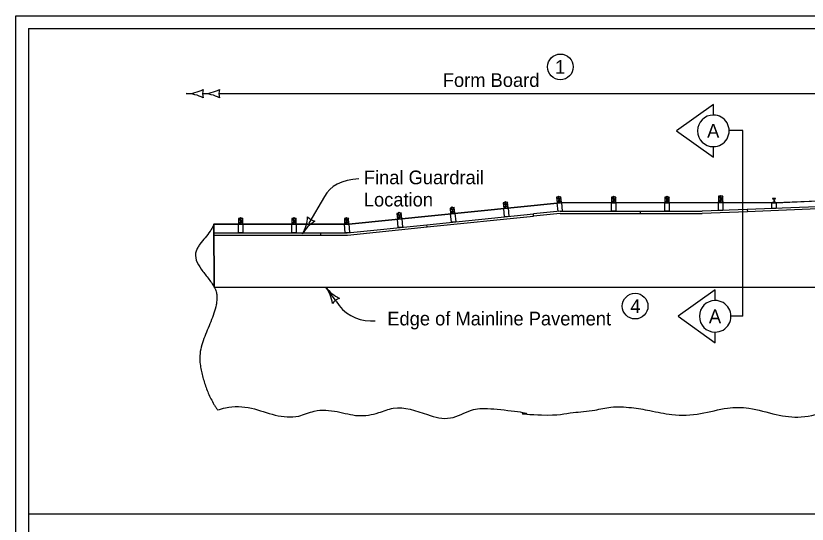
# Model space of a CAD drawing. Extents: x 9538 to 81668, y 7600 to 11751.
# Drawn here: x 10133 to 11058, y 9349 to 9944 of the extents above; entities that cross this region are included whole.
import ezdxf

# ---------------------------------------------------------------- set-up
doc = ezdxf.new("R2010")
doc.units = 0
for name, color, linetype in [('Default', 7, 'Continuous'), ('DsnShtMinorGrid13', 7, 'Continuous'), ('DsnShtMinorGrid14', 7, 'Continuous'), ('dsnStdCells', 7, 'Continuous'), ('dsnStdDimension', 7, 'Continuous'), ('dsnStdNameDate', 7, 'Continuous'), ('dsnStdNote', 7, 'Continuous'), ('dsnStdPattern', 7, 'Continuous'), ('dsnStdShading', 7, 'Continuous'), ('dsnStdTable', 7, 'Continuous')]:
    doc.layers.add(name, color=color, linetype=linetype)

msp = doc.modelspace()

# ---------------------------------------------------------------- linework, layer by layer
at = {"layer": 'Default'}
msp.add_lwpolyline([(10132.52, 9944.02), (13267.53, 9944.02), (13267.53, 7924.02), (10132.52, 7924.02)], close=True, dxfattribs=at)
at = {"layer": 'DsnShtMinorGrid13'}
for centre in [(10769.19, 9884.28), (10856.61, 9604.4)]:
    msp.add_circle(centre, 15, dxfattribs=at)
at = {"layer": 'DsnShtMinorGrid14'}
for p, q in [((10956.48, 9733.86), (10956.48, 9733.93)), ((10702.37, 9725.42), (10708.01, 9719.29)), ((10707.34, 9725.92), (10703.04, 9718.79)), ((10704.76, 9726.64), (10704.75, 9726.71)), ((10705.52, 9719.04), (10704.86, 9725.67)), ((10764.83, 9731.7), (10770.47, 9725.56)), ((10769.81, 9732.2), (10765.5, 9725.07)), ((10765.5, 9725.07), (10770.48, 9725.56)), ((10767.99, 9725.32), (10765.5, 9725.07)), ((10767.99, 9725.32), (10765.5, 9725.07)), ((10766.49, 9715.11), (10765.5, 9725.07)), ((10767.22, 9732.92), (10767.22, 9732.99)), ((10767.98, 9725.32), (10767.32, 9731.95)), ((10770.48, 9725.56), (10771.47, 9715.61)), ((10828.98, 9732.03), (10833.98, 9725.37)), ((10833.98, 9732.03), (10828.98, 9725.37)), ((10828.98, 9725.37), (10833.98, 9725.37)), ((10828.98, 9715.36), (10828.98, 9725.37)), ((10831.48, 9733), (10831.48, 9733.07)), ((10831.48, 9725.37), (10831.48, 9732.03)), ((10833.98, 9725.37), (10833.98, 9715.36)), ((10891.48, 9732.03), (10896.48, 9725.37)), ((10896.48, 9732.03), (10891.48, 9725.37)), ((10891.48, 9725.37), (10896.49, 9725.37)), ((10891.48, 9715.36), (10891.48, 9725.37)), ((10893.98, 9733), (10893.98, 9733.07)), ((10893.98, 9725.37), (10893.98, 9732.03)), ((10896.49, 9725.37), (10896.49, 9715.36)), ((10953.98, 9732.89), (10958.98, 9726.23)), ((10958.98, 9732.89), (10953.98, 9726.23)), ((10953.98, 9726.23), (10958.99, 9726.23)), ((10953.98, 9716.22), (10953.98, 9726.23)), ((10956.48, 9726.23), (10956.48, 9732.89)), ((10958.99, 9726.23), (10958.99, 9716.22)), ((10640.18, 9719.17), (10645.82, 9713.04)), ((10645.16, 9719.67), (10640.85, 9712.54)), ((10642.57, 9720.39), (10642.57, 9720.46)), ((10643.34, 9712.79), (10642.67, 9719.42)), ((10703.04, 9718.79), (10708.02, 9719.29)), ((10704.04, 9708.83), (10703.04, 9718.79)), ((10708.02, 9719.29), (10709.02, 9709.33)), ((10768.98, 9715.36), (10737.62, 9712.2)), ((10771.47, 9715.61), (10766.49, 9715.11)), ((10768.98, 9715.36), (10862.73, 9715.36)), ((10833.98, 9715.36), (10828.98, 9715.36)), ((10862.73, 9712.64), (10862.73, 9715.36)), ((10862.73, 9715.36), (10934.97, 9715.36)), ((10862.73, 9712.65), (10862.73, 9715.36)), ((10896.49, 9715.36), (10891.48, 9715.36)), ((10958.99, 9716.22), (10953.98, 9716.22)), ((10392.74, 9706.96), (10397.74, 9700.29)), ((10397.74, 9706.96), (10392.74, 9700.29)), ((10395.24, 9707.93), (10395.24, 9708)), ((10395.24, 9700.29), (10395.24, 9706.96)), ((10455.24, 9706.96), (10460.24, 9700.29)), ((10460.24, 9706.96), (10455.24, 9700.29)), ((10457.74, 9707.93), (10457.74, 9708)), ((10457.74, 9700.29), (10457.74, 9706.96)), ((10516.63, 9707.02), (10521.95, 9700.58)), ((10521.62, 9707.27), (10516.96, 9700.33)), ((10519.08, 9708.12), (10519.07, 9708.19)), ((10519.46, 9700.45), (10519.12, 9707.15)), ((10578, 9712.96), (10583.64, 9706.79)), ((10582.98, 9713.46), (10578.67, 9706.29)), ((10578.67, 9706.29), (10583.65, 9706.79)), ((10579.66, 9696.28), (10578.67, 9706.29)), ((10580.4, 9714.18), (10580.39, 9714.25)), ((10581.16, 9706.54), (10580.49, 9713.21)), ((10583.65, 9706.79), (10584.64, 9696.78)), ((10613.25, 9699.7), (10737.62, 9712.2)), ((10613.52, 9697.01), (10737.89, 9709.51)), ((10640.85, 9712.54), (10645.83, 9713.04)), ((10641.85, 9702.58), (10640.85, 9712.54)), ((10645.83, 9713.04), (10646.83, 9703.08)), ((10709.02, 9709.33), (10704.04, 9708.83)), ((10737.89, 9709.51), (10737.62, 9712.2)), ((10737.89, 9709.52), (10737.62, 9712.2)), ((10768.98, 9712.65), (10737.89, 9709.52)), ((10768.98, 9712.65), (10862.73, 9712.65)), ((10862.73, 9712.65), (10934.99, 9712.65)), ((10392.74, 9700.29), (10397.74, 9700.29)), ((10392.74, 9690.28), (10392.74, 9700.29)), ((10397.74, 9700.29), (10397.74, 9690.28)), ((10455.24, 9700.29), (10460.24, 9700.29)), ((10455.24, 9690.28), (10455.24, 9700.29)), ((10460.24, 9700.29), (10460.24, 9690.28)), ((10516.96, 9700.33), (10521.96, 9700.58)), ((10517.46, 9690.28), (10516.96, 9700.33)), ((10519.97, 9690.28), (10613.25, 9699.7)), ((10520.24, 9687.57), (10613.52, 9697)), ((10521.96, 9700.58), (10522.45, 9690.53)), ((10584.64, 9696.78), (10579.66, 9696.28)), ((10613.52, 9697), (10613.25, 9699.7)), ((10613.52, 9697.01), (10613.25, 9699.7)), ((10646.83, 9703.08), (10641.85, 9702.58)), ((10363.99, 9690.28), (10488.99, 9690.28)), ((10363.99, 9687.57), (10363.99, 9690.28)), ((10363.99, 9687.57), (10488.99, 9687.57)), ((10397.74, 9690.28), (10392.74, 9690.28)), ((10460.24, 9690.28), (10455.24, 9690.28)), ((10488.99, 9690.28), (10519.97, 9690.28)), ((10488.99, 9687.57), (10488.99, 9690.28)), ((10488.99, 9687.57), (10520.24, 9687.57)), ((10522.45, 9690.53), (10517.46, 9690.28))]:
    msp.add_line(p, q, dxfattribs=at)
for points in [[(10956.29, 9733.32), (10956.29, 9733.86), (10956.68, 9733.86), (10956.68, 9733.32)], [(10704.53, 9725.64), (10704.48, 9726.07), (10705.15, 9726.13), (10705.19, 9725.7)], [(10704.62, 9726.08), (10704.57, 9726.62), (10704.95, 9726.66), (10705.01, 9726.12)], [(10766.99, 9731.92), (10766.95, 9732.34), (10767.61, 9732.41), (10767.65, 9731.98)], [(10767.09, 9732.36), (10767.03, 9732.9), (10767.42, 9732.94), (10767.47, 9732.4)], [(10831.15, 9732.03), (10831.15, 9732.46), (10831.81, 9732.46), (10831.81, 9732.03)], [(10831.29, 9732.46), (10831.29, 9733), (10831.68, 9733), (10831.68, 9732.46)], [(10893.65, 9732.03), (10893.65, 9732.46), (10894.32, 9732.46), (10894.32, 9732.03)], [(10893.79, 9732.46), (10893.79, 9733), (10894.18, 9733), (10894.18, 9732.46)], [(10956.15, 9732.89), (10956.15, 9733.32), (10956.82, 9733.32), (10956.82, 9732.89)], [(10642.34, 9719.39), (10642.3, 9719.82), (10642.96, 9719.88), (10643, 9719.45)], [(10642.43, 9719.83), (10642.38, 9720.37), (10642.77, 9720.41), (10642.82, 9719.87)], [(10394.9, 9706.96), (10394.9, 9707.39), (10395.57, 9707.39), (10395.57, 9706.96)], [(10395.04, 9707.39), (10395.04, 9707.93), (10395.43, 9707.93), (10395.43, 9707.39)], [(10457.4, 9706.96), (10457.4, 9707.39), (10458.07, 9707.39), (10458.07, 9706.96)], [(10457.54, 9707.39), (10457.54, 9707.93), (10457.93, 9707.93), (10457.93, 9707.39)], [(10518.79, 9707.13), (10518.77, 9707.56), (10519.44, 9707.59), (10519.46, 9707.16)], [(10518.91, 9707.57), (10518.88, 9708.11), (10519.27, 9708.13), (10519.3, 9707.59)], [(10580.16, 9713.17), (10580.12, 9713.61), (10580.78, 9713.67), (10580.82, 9713.24)], [(10580.26, 9713.62), (10580.2, 9714.16), (10580.59, 9714.2), (10580.64, 9713.66)], [(10519.46, 9700.45), (10516.96, 9700.33), (10516.96, 9700.33)]]:
    msp.add_lwpolyline(points, dxfattribs=at)
for points in [[(10703.04, 9718.79), (10708.01, 9719.29), (10707.34, 9725.92), (10702.37, 9725.42)], [(10765.5, 9725.07), (10770.47, 9725.56), (10769.81, 9732.2), (10764.83, 9731.7)], [(10828.98, 9725.37), (10833.98, 9725.37), (10833.98, 9732.03), (10828.98, 9732.03)], [(10891.48, 9725.37), (10896.48, 9725.37), (10896.48, 9732.03), (10891.48, 9732.03)], [(10953.98, 9726.23), (10958.98, 9726.23), (10958.98, 9732.89), (10953.98, 9732.89)], [(10640.85, 9712.54), (10645.82, 9713.04), (10645.16, 9719.67), (10640.18, 9719.17)], [(10392.74, 9700.29), (10397.74, 9700.29), (10397.74, 9706.96), (10392.74, 9706.96)], [(10455.24, 9700.29), (10460.24, 9700.29), (10460.24, 9706.96), (10455.24, 9706.96)], [(10516.96, 9700.33), (10521.95, 9700.58), (10521.62, 9707.27), (10516.63, 9707.02)], [(10578.67, 9706.29), (10583.64, 9706.79), (10582.98, 9713.46), (10578, 9712.96)]]:
    msp.add_lwpolyline(points, close=True, dxfattribs=at)
at = {"layer": 'dsnStdCells'}
for p, q in [((11016.43, 9718.72), (11016.43, 9725.68)), ((11016.43, 9725.68), (11017.05, 9725.68)), ((11017.05, 9725.37), (11017.05, 9725.68)), ((11020.8, 9725.37), (11017.05, 9725.37)), ((11020.7, 9730.26), (11017.36, 9730.26)), ((11017.36, 9730.26), (11017.36, 9730.1)), ((11017.36, 9730.26), (11017.36, 9730.1)), ((11020.7, 9730.26), (11017.36, 9730.26)), ((11017.36, 9730.1), (11018.54, 9730.1)), ((11017.36, 9730.1), (11018.54, 9730.1)), ((11018.54, 9725.52), (11017.36, 9725.52)), ((11017.36, 9725.52), (11017.36, 9725.37)), ((11017.36, 9725.52), (11017.36, 9725.37)), ((11018.54, 9725.52), (11017.36, 9725.52)), ((11017.36, 9725.37), (11020.7, 9725.37)), ((11017.36, 9725.37), (11020.7, 9725.37)), ((11018.95, 9729.69), (11018.95, 9725.94)), ((11018.95, 9729.69), (11018.95, 9725.94)), ((11019.11, 9725.94), (11019.11, 9729.69)), ((11019.11, 9725.94), (11019.11, 9729.69)), ((11019.35, 9726.04), (11019.26, 9725.99)), ((11019.35, 9726.04), (11019.26, 9725.99)), ((11019.26, 9725.99), (11019.26, 9725.61)), ((11019.26, 9725.61), (11019.26, 9725.99)), ((11019.35, 9726.04), (11020.31, 9726.04)), ((11020.31, 9726.04), (11019.35, 9726.04)), ((11019.53, 9730.1), (11020.7, 9730.1)), ((11019.53, 9730.1), (11020.7, 9730.1)), ((11020.7, 9725.52), (11019.53, 9725.52)), ((11020.7, 9725.52), (11019.53, 9725.52)), ((11019.56, 9725.99), (11019.56, 9725.57)), ((11019.56, 9725.57), (11019.56, 9725.99)), ((11019.56, 9725.57), (11019.56, 9725.99)), ((11020.12, 9727.55), (11019.6, 9727.55)), ((11019.6, 9727.55), (11019.6, 9726.04)), ((11020.12, 9727.55), (11019.6, 9727.55)), ((11019.6, 9727.55), (11019.6, 9726.04)), ((11019.6, 9726.04), (11020.12, 9726.04)), ((11020.12, 9726.04), (11020.12, 9727.55)), ((11020.12, 9726.04), (11020.12, 9727.55)), ((11020.17, 9725.57), (11020.17, 9725.99)), ((11020.17, 9725.99), (11020.17, 9725.57)), ((11020.17, 9725.57), (11020.17, 9725.99)), ((11020.31, 9726.04), (11020.38, 9726.04)), ((11020.38, 9726.04), (11020.31, 9726.04)), ((11020.47, 9725.99), (11020.38, 9726.04)), ((11020.47, 9725.99), (11020.38, 9726.04)), ((11020.38, 9725.52), (11020.47, 9725.57)), ((11020.38, 9725.52), (11020.47, 9725.57)), ((11020.47, 9725.57), (11020.47, 9725.99)), ((11020.47, 9725.57), (11020.47, 9725.99)), ((11020.7, 9730.1), (11020.7, 9730.26)), ((11020.7, 9730.1), (11020.7, 9730.26)), ((11020.7, 9725.37), (11020.7, 9725.52)), ((11020.7, 9725.37), (11020.7, 9725.52)), ((11020.8, 9725.68), (11021.43, 9725.68)), ((11020.8, 9725.68), (11020.8, 9725.37)), ((11021.43, 9725.68), (11021.43, 9718.72)), ((11021.43, 9718.72), (11016.43, 9718.72))]:
    msp.add_line(p, q, dxfattribs=at)
for points in [[(11019.26, 9725.61), (11019.26, 9725.61)], [(11019.53, 9725.52), (11020.38, 9725.52), (11020.38, 9725.52)]]:
    msp.add_lwpolyline(points, dxfattribs=at)
for centre, start, end in [((11018.54, 9729.69), 359.99336, 90.00253), ((11018.54, 9729.69), 359.99336, 90.00253), ((11018.54, 9725.94), 270.00734, 359.99635), ((11018.54, 9725.94), 270.00734, 359.99635), ((11019.53, 9729.69), 90.00734, 179.99635), ((11019.53, 9729.69), 90.00734, 179.99635), ((11019.53, 9725.94), 179.99336, 270.00253), ((11019.53, 9725.94), 179.99336, 270.00253), ((11019.53, 9725.94), 230.88662, 270.00253)]:
    msp.add_arc(centre, 0.417, start, end, dxfattribs=at)
for points in [[(11019.56, 9725.99), (11019.54, 9726), (11019.49, 9726.03), (11019.41, 9726.05), (11019.33, 9726.03), (11019.29, 9726), (11019.26, 9725.99)], [(11019.56, 9725.99), (11019.54, 9726), (11019.49, 9726.03), (11019.41, 9726.05), (11019.33, 9726.03), (11019.29, 9726), (11019.26, 9725.99)], [(11019.26, 9725.99), (11019.29, 9726), (11019.33, 9726.03), (11019.41, 9726.05), (11019.49, 9726.03), (11019.54, 9726), (11019.56, 9725.99)], [(11019.46, 9725.53), (11019.47, 9725.53), (11019.51, 9725.54), (11019.54, 9725.56), (11019.56, 9725.57)], [(11020.17, 9725.99), (11020.11, 9726), (11020.01, 9726.03), (11019.85, 9726.04), (11019.7, 9726.03), (11019.61, 9726), (11019.56, 9725.99)], [(11020.17, 9725.99), (11020.11, 9726), (11020.01, 9726.03), (11019.85, 9726.04), (11019.7, 9726.03), (11019.61, 9726), (11019.56, 9725.99)], [(11019.56, 9725.99), (11019.61, 9726), (11019.7, 9726.03), (11019.85, 9726.04), (11020.01, 9726.03), (11020.11, 9726), (11020.17, 9725.99)], [(11019.56, 9725.57), (11019.62, 9725.56), (11019.72, 9725.53), (11019.88, 9725.52), (11020.03, 9725.54), (11020.12, 9725.56), (11020.17, 9725.57)], [(11020.17, 9725.57), (11020.12, 9725.56), (11020.03, 9725.54), (11019.88, 9725.52), (11019.72, 9725.53), (11019.62, 9725.56), (11019.56, 9725.57)], [(11019.56, 9725.57), (11019.62, 9725.56), (11019.72, 9725.53), (11019.88, 9725.52), (11020.03, 9725.54), (11020.12, 9725.56), (11020.17, 9725.57)], [(11020.47, 9725.99), (11020.45, 9726), (11020.41, 9726.02), (11020.35, 9726.04), (11020.28, 9726.04), (11020.21, 9726.02), (11020.18, 9726), (11020.17, 9725.99)], [(11020.47, 9725.99), (11020.45, 9726), (11020.41, 9726.02), (11020.35, 9726.04), (11020.28, 9726.04), (11020.21, 9726.02), (11020.18, 9726), (11020.17, 9725.99)], [(11020.17, 9725.99), (11020.18, 9726), (11020.21, 9726.02), (11020.28, 9726.04), (11020.35, 9726.04), (11020.41, 9726.02), (11020.45, 9726), (11020.47, 9725.99)], [(11020.17, 9725.57), (11020.18, 9725.57), (11020.21, 9725.55), (11020.28, 9725.52), (11020.35, 9725.52), (11020.41, 9725.54), (11020.45, 9725.56), (11020.47, 9725.57)], [(11020.47, 9725.57), (11020.45, 9725.56), (11020.41, 9725.54), (11020.35, 9725.52), (11020.28, 9725.52), (11020.21, 9725.55), (11020.18, 9725.57), (11020.17, 9725.57)], [(11020.17, 9725.57), (11020.18, 9725.57), (11020.21, 9725.55), (11020.28, 9725.52), (11020.35, 9725.52), (11020.41, 9725.54), (11020.45, 9725.56), (11020.47, 9725.57)]]:
    msp.add_open_spline(points, degree=3, dxfattribs=at)
at = {"layer": 'dsnStdDimension'}
msp.add_line((10370.79, 9853.15), (11393.21, 9853.15), dxfattribs=at)
for centre, radius, start, end in [((10331.57, 9895.5), 42.5, 270, 298.07249), ((10350.79, 9895.5), 42.5, 270, 298.07249), ((10367.21, 9853), 16.42, 162.26665, 197.73335), ((10386.43, 9853), 16.42, 162.26665, 197.73335), ((10331.57, 9810.5), 42.5, 61.92751, 90), ((10350.79, 9810.5), 42.5, 61.92751, 90)]:
    msp.add_arc(centre, radius, start, end, dxfattribs=at)
at = {"layer": 'dsnStdNameDate'}
for p, q in [((11496.09, 9744.89), (11020.8, 9725.37)), ((10769.52, 9725.37), (10521.73, 9700.29)), ((11020.8, 9725.37), (10769.52, 9725.37)), ((10521.73, 9700.29), (10363.99, 9700.29)), ((10363.99, 9700.29), (10364.45, 9626.66)), ((10364.45, 9626.66), (10363.99, 9700.29)), ((10364.45, 9626.66), (11496.09, 9626.66)), ((12303.1, 9361.02), (10147.52, 9361.02))]:
    msp.add_line(p, q, dxfattribs=at)
msp.add_spline([(10363.99, 9700.29), (10362.18, 9696.07), (10359.73, 9692.06), (10353.75, 9684.41), (10347.71, 9676.81), (10345.21, 9672.86), (10344.18, 9670.83), (10343.74, 9669.79), (10343.53, 9669.26), (10343.43, 9669), (10343.34, 9668.74), (10343.5, 9658.28), (10349.18, 9647.75), (10357.22, 9637.18), (10361.14, 9631.91), (10364.45, 9626.66)], degree=3, dxfattribs=at)
at = {"layer": 'dsnStdNote'}
for p, q in [((10493.5, 9732.66), (10474.95, 9701.32)), ((10507.12, 9610.21), (10495, 9626.66)), ((10547.2, 9587.14), (10552.65, 9587.14))]:
    msp.add_line(p, q, dxfattribs=at)
for centre, radius, start, end in [((10431.19, 9710.82), 42.5, 329.37973, 357.45222), ((10485.91, 9719.84), 16.42, 221.64638, 257.11308), ((10504.34, 9667.53), 42.5, 121.30724, 149.37973), ((10529.22, 9651.86), 42.5, 216.37256, 244.44505), ((10460.78, 9601.45), 42.5, 8.30007, 36.37256), ((10516.14, 9597.97), 16.42, 108.63921, 144.10591), ((10547.26, 9633.6), 46.46, 210.22743, 270)]:
    msp.add_arc(centre, radius, start, end, dxfattribs=at)
msp.add_ellipse((10574.59, 9693.62), major_axis=(-81.09, 39.04), ratio=0.555556, start_param=5.482641, end_param=6.283185, dxfattribs=at)
at = {"layer": 'dsnStdPattern'}
for p, q in [((10982.61, 9809.76), (10966.83, 9809.76)), ((10982.61, 9592.47), (10982.61, 9809.76)), ((10982.61, 9592.47), (10968.65, 9592.47))]:
    msp.add_line(p, q, dxfattribs=at)
for points in [[(10948.04, 9827.94), (10948.04, 9840.26), (10904.91, 9809.45), (10948.04, 9778.64), (10948.04, 9790.97)], [(10950.17, 9610.96), (10950.17, 9623.28), (10907.03, 9592.47), (10950.17, 9561.66), (10950.17, 9573.99)]]:
    msp.add_lwpolyline(points, dxfattribs=at)
for centre, start, end in [((10948.04, 9809.45), 90.00083, 269.99917), ((10948.04, 9809.45), 269.99917, 90.00083), ((10950.17, 9592.47), 90.00083, 269.99917), ((10950.17, 9592.47), 269.99917, 90.00083)]:
    msp.add_arc(centre, 18.49, start, end, dxfattribs=at)
at = {"layer": 'dsnStdShading'}
for q in [(10147.52, 8319.02), (13243.21, 9929.02)]:
    msp.add_line((10147.52, 9929.02), q, dxfattribs=at)
at = {"layer": 'dsnStdTable'}
for p, q in [((11020.7, 9725.37), (11496.09, 9744.89)), ((11399.3, 9733.93), (10987.73, 9717.47)), ((10521.73, 9700.29), (10769.52, 9725.37)), ((11017.36, 9725.37), (10769.52, 9725.37)), ((11399.41, 9731.22), (10987.73, 9714.76)), ((11016.43, 9718.72), (11016.43, 9725.68)), ((11016.43, 9725.68), (11017.05, 9725.68)), ((11017.05, 9725.37), (11017.05, 9725.68)), ((11020.8, 9725.37), (11017.05, 9725.37)), ((11017.36, 9730.26), (11017.36, 9730.1)), ((11020.7, 9730.26), (11017.36, 9730.26)), ((11017.36, 9730.1), (11018.54, 9730.1)), ((11017.36, 9725.52), (11017.36, 9725.37)), ((11018.54, 9725.52), (11017.36, 9725.52)), ((11017.36, 9725.37), (11020.7, 9725.37)), ((11018.95, 9729.69), (11018.95, 9725.94)), ((11019.11, 9725.94), (11019.11, 9729.69)), ((11019.35, 9726.04), (11019.26, 9725.99)), ((11019.26, 9725.61), (11019.26, 9725.99)), ((11019.35, 9726.04), (11020.31, 9726.04)), ((11019.53, 9730.1), (11020.7, 9730.1)), ((11020.7, 9725.52), (11019.53, 9725.52)), ((11019.56, 9725.57), (11019.56, 9725.99)), ((11020.12, 9727.55), (11019.6, 9727.55)), ((11019.6, 9727.55), (11019.6, 9726.04)), ((11020.12, 9726.04), (11020.12, 9727.55)), ((11020.17, 9725.57), (11020.17, 9725.99)), ((11020.31, 9726.04), (11020.38, 9726.04)), ((11020.47, 9725.99), (11020.38, 9726.04)), ((11020.38, 9725.52), (11020.47, 9725.57)), ((11020.47, 9725.57), (11020.47, 9725.99)), ((11020.7, 9730.1), (11020.7, 9730.26)), ((11020.7, 9725.37), (11020.7, 9725.52)), ((11020.8, 9725.68), (11021.43, 9725.68)), ((11020.8, 9725.68), (11020.8, 9725.37)), ((11021.43, 9725.68), (11021.43, 9718.72)), ((10987.73, 9717.47), (10934.97, 9715.36)), ((10987.73, 9717.47), (10987.84, 9714.76)), ((10987.73, 9717.47), (10987.84, 9714.76)), ((11021.43, 9718.72), (11016.43, 9718.72)), ((10987.84, 9714.76), (10934.99, 9712.65)), ((10363.99, 9700.29), (10521.73, 9700.29)), ((10364.45, 9626.66), (11977.72, 9626.66))]:
    msp.add_line(p, q, dxfattribs=at)
for centre, start, end in [((11018.54, 9729.69), 359.99336, 90.00253), ((11018.54, 9725.94), 270.00734, 359.99635), ((11019.53, 9729.69), 90.00734, 179.99635), ((11019.53, 9725.94), 264.71743, 270.00253)]:
    msp.add_arc(centre, 0.417, start, end, dxfattribs=at)
for points in [[(11019.56, 9725.99), (11019.54, 9726), (11019.49, 9726.03), (11019.41, 9726.05), (11019.33, 9726.03), (11019.29, 9726), (11019.26, 9725.99)], [(11019.46, 9725.53), (11019.47, 9725.53), (11019.51, 9725.54), (11019.54, 9725.56), (11019.56, 9725.57)], [(11020.17, 9725.99), (11020.11, 9726), (11020.01, 9726.03), (11019.85, 9726.04), (11019.7, 9726.03), (11019.61, 9726), (11019.56, 9725.99)], [(11019.56, 9725.57), (11019.62, 9725.56), (11019.72, 9725.53), (11019.88, 9725.52), (11020.03, 9725.54), (11020.12, 9725.56), (11020.17, 9725.57)], [(11020.47, 9725.99), (11020.45, 9726), (11020.41, 9726.02), (11020.35, 9726.04), (11020.28, 9726.04), (11020.21, 9726.02), (11020.18, 9726), (11020.17, 9725.99)], [(11020.17, 9725.57), (11020.18, 9725.57), (11020.21, 9725.55), (11020.28, 9725.52), (11020.35, 9725.52), (11020.41, 9725.54), (11020.45, 9725.56), (11020.47, 9725.57)]]:
    msp.add_open_spline(points, degree=3, dxfattribs=at)
for points in [[(10363.99, 9700.29), (10362.18, 9696.07), (10359.73, 9692.06), (10353.75, 9684.41), (10347.71, 9676.81), (10345.21, 9672.86), (10344.18, 9670.83), (10343.74, 9669.79), (10343.53, 9669.26), (10343.43, 9669), (10343.34, 9668.74), (10343.5, 9658.28), (10349.18, 9647.75), (10357.22, 9637.18), (10361.14, 9631.91), (10364.45, 9626.66)], [(10364.45, 9626.66), (10365.85, 9623.93), (10366.83, 9621.19), (10367.63, 9617.04), (10367.7, 9615.65), (10367.47, 9610.8), (10366.75, 9605.92), (10364.12, 9596.1), (10356.33, 9576.3), (10349.29, 9556.39), (10347.61, 9546.45), (10348, 9536.55), (10349.27, 9529.64), (10350.82, 9522.78), (10354.93, 9509.25), (10360.64, 9495.96), (10364.2, 9489.42), (10366.17, 9486.17), (10368.28, 9482.94)], [(10368.28, 9482.94), (10377.7, 9485.52), (10407.92, 9484.95), (10435.86, 9476.96), (10463.24, 9475.82), (10481.48, 9481.53), (10508.28, 9480.96), (10532.8, 9476.39), (10556.75, 9479.81), (10573.86, 9484.95), (10613.78, 9477.53), (10640.58, 9473.54), (10665.1, 9482.67), (10687.91, 9484.38), (10726.68, 9478.67), (10726.11, 9478.67), (10747.27, 9477.07), (10784.33, 9479.92), (10809.42, 9482.78), (10828.24, 9486.2), (10852.19, 9485.63), (10873.86, 9482.21), (10899.52, 9477.64), (10933.16, 9478.78), (10964.52, 9485.06), (10989.61, 9485.06), (11021.55, 9477.64), (11050.63, 9474.79), (11084.27, 9481.63), (11116.77, 9485.06), (11150.99, 9478.21), (11176.65, 9475.36), (11198.89, 9478.78), (11226.83, 9494.19), (11237.09, 9496.47), (11261.61, 9498.75), (11292.28, 9499.32), (11313.37, 9499.32), (11366.68, 9490.03)]]:
    msp.add_spline(points, degree=3, dxfattribs=at)

# ---------------------------------------------------------------- texts
at = {"layer": 'DsnShtMinorGrid13'}
for s, p in [('1', (10762.96, 9876.28)), ('4', (10850.98, 9596.4))]:
    msp.add_text(s, height=16, dxfattribs=at).set_placement(p)
at = {"layer": 'dsnStdDimension'}
msp.add_text('Form Board', height=16, dxfattribs=at).set_placement((10631.74, 9860.84))
at = {"layer": 'dsnStdNote'}
for s, p in [('Final Guardrail ', (10539.4, 9746.99)), ('Location', (10539.4, 9720.99)), ('Edge of Mainline Pavement', (10566.84, 9581.87))]:
    msp.add_text(s, height=16, dxfattribs=at).set_placement(p)
at = {"layer": 'dsnStdPattern'}
for p in [(10940.77, 9801.45), (10942.86, 9584.47)]:
    msp.add_text('A', height=16, dxfattribs=at).set_placement(p)

doc.saveas('drawing.dxf')
